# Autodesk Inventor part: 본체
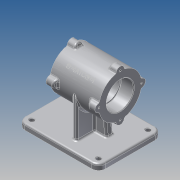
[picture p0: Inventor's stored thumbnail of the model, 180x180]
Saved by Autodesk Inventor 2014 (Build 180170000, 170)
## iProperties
Created: 2015-12
Part Number: 본체
Material: Aluminum 6061
Document SubType Name: Modeling
Designer: user
Density: 2.71 g/cm^3
Appearance: Aluminum - Flat
Mass: 1164.64 g
Surface Area: 814.792 cm^2
Volume: 429.757 cm^3
Author: user
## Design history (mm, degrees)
sketch "Sketch1"
  geometry: C1 r 37 at (0, 0); 1 further point
  constraints: 1 centre point, 1 coincident
  dimensions: "d0" = 74 diameter of C1
extrude "Extrusion1" new body sketch "Sketch1" stored distance "d1" = 85; taper "d2" = 0 deg
workplane "Work Plane1"
sketch "Sketch2"
  geometry: L1 (-37, 0)-(-37, -80); L2 (-37, -80)-(37, -80); L3 (37, 0)-(37, -80); L4 (37, 0)-(-37, 0); A1 r 37 centre (0, 0) between (-37, 0) and (37, 0) reference; 1 further point
  constraints: 8 end point, 2 point on circle
  dimensions: "d3" = 80 distance from line of A1.centre L2
extrude "Extrusion2" join sketch "Sketch2" stored distance "d4" = 8; taper "d5" = 0 deg
sketch "Sketch3"
  geometry: L1 (74, -8)-(74, 0) reference; L2 (0, 0)-(74, 0) reference; L3 (0, -8)-(0, 0) reference; L4 (74, -8)-(0, -8) reference; L5 (-6, 56)-(80, 56); L6 (92, 44)-(92, -72); L7 (80, -84)-(-6, -84); L8 (-18, -72)-(-18, 44); A1 r 12 centre (80, 44) between (92, 44) and (80, 56); A2 r 12 centre (-6, 44) between (-6, 56) and (-18, 44); A3 r 12 centre (-6, -72) between (-18, -72) and (-6, -84); A4 r 12 centre (80, -72) between (80, -84) and (92, -72); 5 further points
  constraints: 8 end point, 8 point on circle, 8 point on line, 8 tangent, 4 centre point, 3 equal radius
  dimensions: "d6" = 140 distance between parallel lines of L7 L5; "d7" = 110 distance between parallel lines of L8 L6; "d10" = 80 distance from line of L7 point (37, -4); "d11" = 55 distance from line of L8 point (37, -4); "d14" = 12 radius of A1
extrude "Extrusion3" join sketch "Sketch3" distance "d12" = 10; taper "d13" = 0 deg
sketch "Sketch4"
  geometry: C1 r 4 at (0, -12); C2 r 4 at (86, -12); C3 r 4 at (86, -128); C4 r 4 at (0, -128); A1 r 12 centre (86, -12) between (98, -12) and (86, 0) reference; A2 r 12 centre (0, -12) between (0, 0) and (-12, -12) reference; A3 r 12 centre (0, -128) between (-12, -128) and (0, -140) reference; A4 r 12 centre (86, -128) between (86, -140) and (98, -128) reference; 1 further point
  constraints: 4 centre point, 4 coincident
  dimensions: "d15" = 8 diameter of C1; "d16" = 8 diameter of C2; "d17" = 8 diameter of C4; "d18" = 8 diameter of C3
extrude "Extrusion4" cut sketch "Sketch4" distance "d19" = 10; taper "d20" = 0 deg
workplane "Work Plane2"
sketch "Sketch5"
  geometry: L1 (-38.5, -37)-(-38.5, 37) reference; L2 (-38.5, 37)-(46.5, 37) reference; L3 (46.5, 37)-(46.5, -37) reference; L4 (46.5, -37)-(8, -37) reference; L5 (8, -37)-(8, -70) reference; L6 (8, -70)-(64, -70) reference; L7 (64, -70)-(64, -80) reference; L8 (64, -80)-(-76, -80) reference; L9 (-76, -80)-(-76, -70) reference; L10 (-76, -70)-(0, -70) reference; L11 (0, -70)-(0, -37) reference; L12 (0, -37)-(-38.5, -37) reference; L13 (29, -70)-(21.765, -11.077); L14 (-21, -70)-(-14.851, -19.921); L15 (-14.851, -19.921)-(21.765, -11.077); L16 (0, -55.098)-(8, -55.098); L17 (4, -55.098)-(4, -48.353); L18 (29, -70)-(-21, -70); 1 further point
  constraints: 12 end point, 4 point on line, 1 midpoint
  dimensions: "d21" = 25 distance from line of L14.start L17; "d22" = 50 distance of L13.start L14.start; "d23" = 97 deg angle of L10 L14; "d24" = 97 deg angle of L6 L13; "d25" = 90 deg angle of L16 L17
extrude "Extrusion5" join sketch "Sketch5" stored distance "d26" = 12; taper "d27" = 0 deg
sketch "Sketch6"
  geometry: C1 r 7 at (0, 37); 1 further point
  constraints: 1 centre point, 1 vertical alignment, 1 other
  dimensions: "d28" = 14 diameter of C1
extrude "Extrusion6" join sketch "Sketch6" distance "d29" = 12; taper "d30" = 0 deg
sketch "Sketch7"
  geometry: L1 (-16.948, -37)-(-38.5, -37) reference; L2 (-38.5, -37)-(-38.5, 37) reference; L3 (-38.5, 37)-(34.5, 37) reference; L4 (34.5, 37)-(34.5, 44) reference; L5 (34.5, 44)-(46.5, 44) reference; L6 (46.5, 44)-(46.5, -37) reference; L7 (46.5, -37)-(24.948, -37) reference; L8 (24.948, -37)-(29, -70) reference; L9 (29, -70)-(64, -70) reference; L10 (64, -70)-(64, -80) reference; L11 (64, -80)-(-76, -80) reference; L12 (-76, -80)-(-76, -70) reference; L13 (-76, -70)-(-21, -70) reference; L14 (-21, -70)-(-16.948, -37) reference; L15 (34.5, 44)-(29.154, 29.313); L16 (29.154, 29.313)-(34.5, 29.313); L17 (34.5, 29.313)-(34.5, 44); 1 further point
  constraints: 6 end point
  dimensions: "d31" = 110 deg angle of L3 L15
extrude "Extrusion7" join sketch "Sketch7" stored distance "d32" = 14; taper "d33" = 0 deg
sketch "Sketch8"
  geometry: L1 (-11.136, 35.284)-(-11.908, 49.217); L2 (-11.908, 49.217)-(13.943, 48.14); L3 (13.943, 48.14)-(11.136, 35.284); A1 r 37 centre (0, 0) between (-6.969, 36.338) and (6.969, 36.338) reference; A2 r 7 centre (0, 37) between (6.969, 36.338) and (-6.969, 36.338) reference
  constraints: 6 end point, 2 point on circle
extrude "Extrusion8" cut sketch "Sketch8" distance "d34" = 19; taper "d35" = 0 deg
pattern_circular "Circular Pattern1" dims "d37" = 360 deg
workplane "Work Plane3"
mirror "Mirror1"
sketch "Sketch9"
  geometry: C1 r 23.5 at (0, 0); A1 r 37 centre (0, 0) between (6.969, -36.338) and (36.338, -6.969) reference
  constraints: 1 centre point, 1 coincident
  dimensions: "d39" = 47 diameter of C1
extrude "Extrusion9" cut sketch "Sketch9" distance "d40" = 22; taper "d41" = 0 deg
sketch "Sketch10"
  geometry: C1 r 23.5 at (0, 0) reference; C2 r 21 at (0, 0)
  constraints: 1 centre point, 1 coincident
  dimensions: "d42" = 42 diameter of C2
extrude "Extrusion10" cut sketch "Sketch10" distance "d43" = 41; taper "d44" = 0 deg
sketch "Sketch11"
  geometry: C1 r 23.5 at (0, 0); A1 r 37 centre (0, 0) between (-6.969, 36.338) and (-36.338, 6.969) reference
  constraints: 1 centre point, 1 coincident
  dimensions: "d45" = 47 diameter of C1
extrude "Extrusion11" cut sketch "Sketch11" distance "d46" = 22; taper "d47" = 0 deg
fillet "Fillet1" dims "d48" = 0.3
chamfer "Chamfer1" distance "d49" = 1; stored, may be unused: second distance "d50" = 2, angle "d51" = 45 deg
sketch "Sketch12"
  geometry: A1 r 7 centre (0, 37) between (6.969, 36.338) and (-6.969, 36.338) reference; A2 r 7 centre (-37, 0) between (-36.338, 6.969) and (-36.338, -6.969) reference; A3 r 7 centre (0, -37) between (-6.969, -36.338) and (6.969, -36.338) reference; A4 r 7 centre (37, 0) between (36.338, -6.969) and (36.338, 6.969) reference
hole "Hole1" sketch "Sketch12" at (0, 37), (37, 0), (0, -37), (-37, 0) diameter "d52" = 3.242; stored, may be unused: countersink angle "d56" = 90 deg, drill point angle "d58" = 118 deg; dims "d53" = 9, "d54" = 4, "d55" = 2, "d57" = 11
mirror "Mirror2"
chamfer "Chamfer2" distance "d59" = 1; stored, may be unused: second distance "d60" = 2, angle "d61" = 45 deg
fillet "Fillet2" dims "d62" = 3
workplane "Work Plane6"
  workplane "Work Plane5"
sketch "Sketch13"
  geometry: 2 further points
  constraints: 1 coincident, 1 other
emboss "Emboss1" sketch "Sketch13" dims "d64" = 0.5, "d65" = 0
fillet "Fillet3" dims "d66" = 3
mirror "Mirror3"
fillet "Fillet4" dims "d67" = 3
fillet "Fillet5" dims "d68" = 3
body "Solid1"
node "Project Cut Edges1"
node "Project Cut Edges2"
node "Project Cut Edges3"
